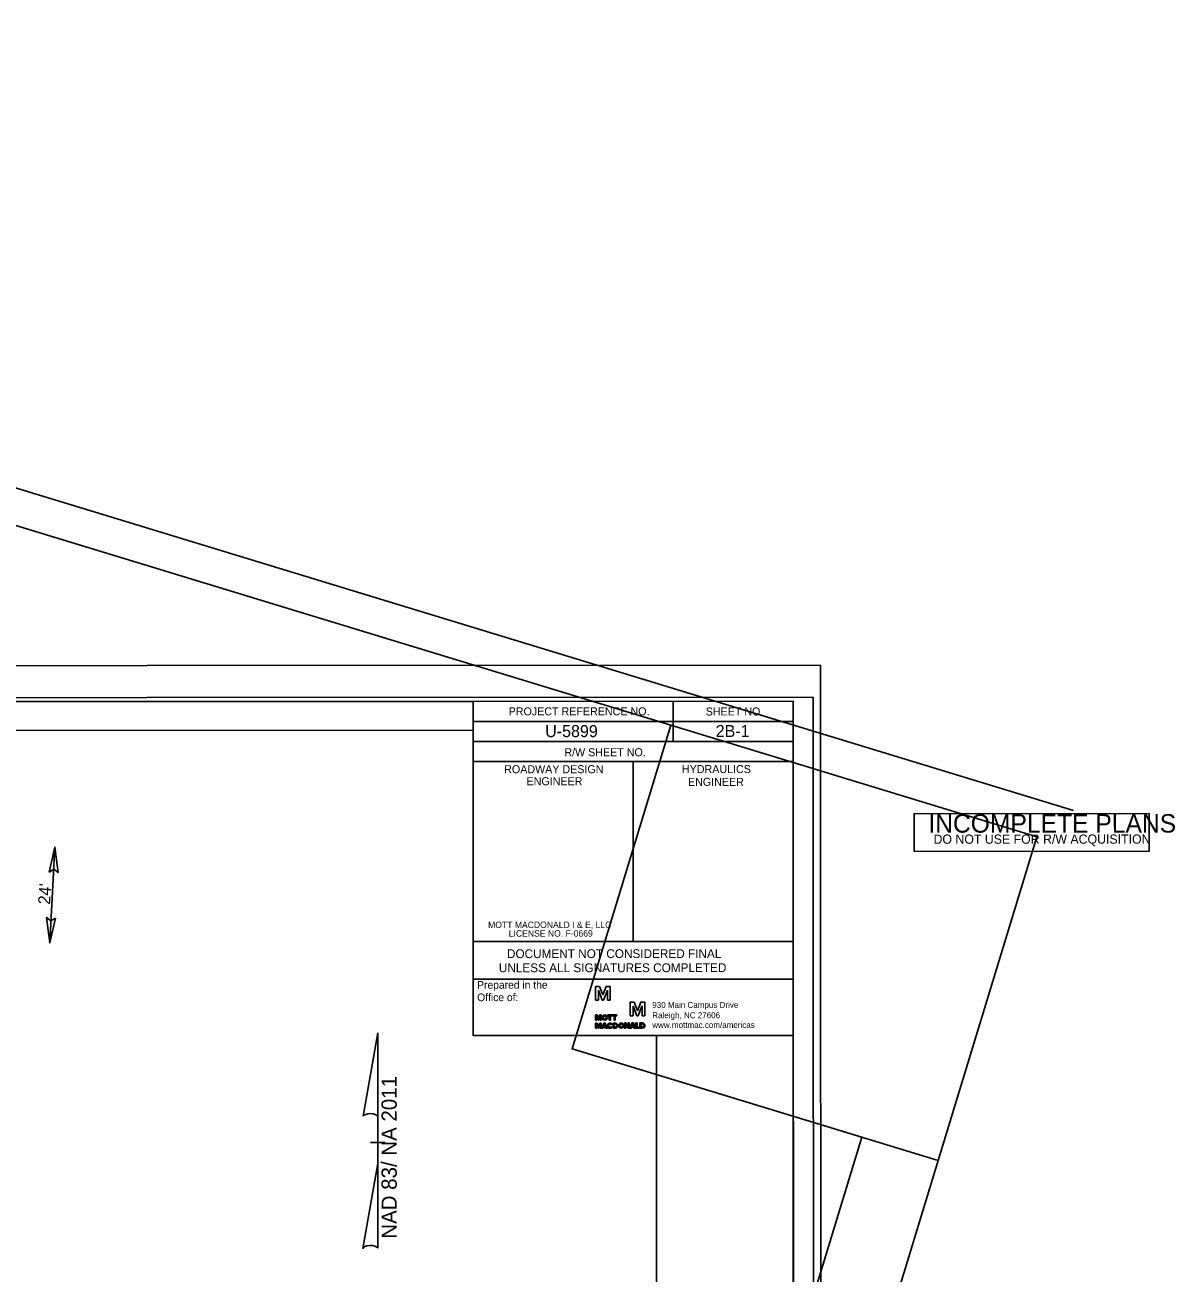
# Model space of a CAD drawing. Extents: x 1443477 to 1619989, y 756574 to 899826.
# Drawn here: x 1619701.9 to 1619989.5, y 898108 to 898420 of the extents above; entities that cross this region are included whole.
import ezdxf

# ---------------------------------------------------------------- set-up
doc = ezdxf.new("R2010")
doc.units = 0
for name, color, linetype in [('Default', 7, 'Continuous'), ('Old_Level_2', 7, 'Continuous'), ('Old_Level_42', 7, 'Continuous'), ('Old_Level_45', 7, 'Continuous'), ('Prop Dimension', 7, 'Continuous'), ('Prop North Arrow NAD83 for Plan Sheets CELL', 7, 'Continuous'), ('Prop Terminator CELL', 7, 'Continuous'), ('Sheet Clip Boundary CELL', 7, 'Continuous'), ('Sheet Cutting Line CELL', 7, 'Continuous'), ('Sheet Data Field CELL', 7, 'Continuous'), ('Sheet Layout Plan Border', 7, 'Continuous'), ('Sheet Plan CELL', 7, 'Continuous'), ('Sheet Plan Layout CELL', 7, 'Continuous'), ('Sheet Plot Border Inside CELL', 7, 'Continuous'), ('Sheet Plot Border Outside CELL', 7, 'Continuous'), ('Sheet Sticker Exception Certification CELL', 7, 'Continuous'), ('Sheet Sticker Incomplete CELL', 7, 'Continuous')]:
    doc.layers.add(name, color=color, linetype=linetype)

msp = doc.modelspace()

# ---------------------------------------------------------------- linework, layer by layer
at = {"layer": 'Default'}
msp.add_lwpolyline([(1619324.8, 898243.59), (1619813.94, 898243.79), (1619813.98, 898167.39), (1619859.81, 898167.41), (1619859.94, 897863.4), (1619324.96, 897863.18)], close=True, dxfattribs=at)
at = {"layer": 'Old_Level_2'}
for p, q in [((1619845.57, 898179.68), (1619844.56, 898179.68)), ((1619844.56, 898179.68), (1619844.56, 898176.28)), ((1619846.39, 898177.58), (1619845.57, 898179.68)), ((1619847.23, 898179.68), (1619846.41, 898177.58)), ((1619848.24, 898179.68), (1619847.23, 898179.68)), ((1619848.24, 898176.28), (1619848.24, 898179.68)), ((1619844.56, 898176.28), (1619845.28, 898176.28)), ((1619845.28, 898176.28), (1619845.28, 898178.73)), ((1619845.28, 898178.73), (1619845.29, 898178.73)), ((1619845.29, 898178.73), (1619846.24, 898176.28)), ((1619846.24, 898176.28), (1619846.56, 898176.28)), ((1619846.39, 898177.55), (1619846.39, 898177.58)), ((1619846.41, 898177.55), (1619846.39, 898177.55)), ((1619846.41, 898177.58), (1619846.41, 898177.55)), ((1619846.56, 898176.28), (1619847.51, 898178.74)), ((1619847.51, 898178.74), (1619847.52, 898178.74)), ((1619847.52, 898178.74), (1619847.52, 898176.28)), ((1619847.52, 898176.28), (1619848.24, 898176.28)), ((1619854.21, 898175.72), (1619853.21, 898175.72)), ((1619853.21, 898175.72), (1619853.21, 898172.32)), ((1619853.92, 898172.32), (1619853.92, 898174.77)), ((1619853.92, 898174.77), (1619853.93, 898174.77)), ((1619853.93, 898174.77), (1619854.89, 898172.32)), ((1619855.04, 898173.62), (1619854.21, 898175.72)), ((1619855.04, 898173.59), (1619855.04, 898173.62)), ((1619855.06, 898173.59), (1619855.04, 898173.59)), ((1619855.88, 898175.73), (1619855.06, 898173.62)), ((1619855.06, 898173.62), (1619855.06, 898173.59)), ((1619855.2, 898172.32), (1619856.16, 898174.78)), ((1619856.89, 898175.73), (1619855.88, 898175.73)), ((1619856.16, 898174.78), (1619856.17, 898174.78)), ((1619856.17, 898174.78), (1619856.17, 898172.33)), ((1619856.89, 898172.33), (1619856.89, 898175.73)), ((1619844.95, 898172.56), (1619844.56, 898172.56)), ((1619844.56, 898172.56), (1619844.56, 898171.26)), ((1619844.56, 898171.26), (1619844.83, 898171.26)), ((1619844.95, 898170.54), (1619844.56, 898170.54)), ((1619844.56, 898170.54), (1619844.56, 898169.24)), ((1619844.83, 898171.26), (1619844.83, 898172.2)), ((1619844.83, 898172.2), (1619844.84, 898172.2)), ((1619844.83, 898172.2), (1619844.84, 898172.2)), ((1619844.83, 898169.24), (1619844.83, 898170.18)), ((1619844.83, 898170.18), (1619844.84, 898170.18)), ((1619844.84, 898172.2), (1619845.21, 898171.26)), ((1619844.84, 898170.18), (1619845.21, 898169.24)), ((1619845.27, 898171.75), (1619844.95, 898172.56)), ((1619845.27, 898169.73), (1619844.95, 898170.54)), ((1619845.21, 898171.26), (1619845.33, 898171.26)), ((1619845.59, 898172.56), (1619845.27, 898171.75)), ((1619845.59, 898170.54), (1619845.27, 898169.73)), ((1619845.33, 898171.26), (1619845.69, 898172.2)), ((1619845.33, 898169.24), (1619845.7, 898170.18)), ((1619845.98, 898172.56), (1619845.59, 898172.56)), ((1619845.98, 898170.54), (1619845.59, 898170.54)), ((1619845.69, 898172.2), (1619845.7, 898172.2)), ((1619845.69, 898172.2), (1619845.7, 898172.2)), ((1619845.69, 898172.2), (1619845.7, 898172.2)), ((1619845.7, 898172.2), (1619845.71, 898171.26)), ((1619845.7, 898170.18), (1619845.71, 898170.18)), ((1619845.71, 898171.26), (1619845.98, 898171.26)), ((1619845.71, 898170.18), (1619845.71, 898169.24)), ((1619845.98, 898171.26), (1619845.98, 898172.56)), ((1619845.98, 898169.24), (1619845.98, 898170.54)), ((1619848.51, 898170.12), (1619848.74, 898170.23)), ((1619849.51, 898170.54), (1619848.92, 898170.54)), ((1619848.92, 898170.54), (1619848.92, 898169.87)), ((1619848.92, 898169.87), (1619848.92, 898169.24)), ((1619849.19, 898169.49), (1619849.19, 898170.3)), ((1619849.19, 898170.3), (1619849.51, 898170.3)), ((1619853.21, 898172.32), (1619853.92, 898172.32)), ((1619854.89, 898172.32), (1619855.2, 898172.32)), ((1619855.65, 898170.55), (1619855.65, 898170.55)), ((1619856.24, 898170.55), (1619855.65, 898170.55)), ((1619855.65, 898170.55), (1619855.65, 898169.87)), ((1619855.65, 898169.87), (1619855.65, 898169.25)), ((1619855.92, 898169.5), (1619855.92, 898170.31)), ((1619855.92, 898170.31), (1619856.24, 898170.31)), ((1619856.17, 898172.33), (1619856.89, 898172.33)), ((1619856.24, 898170.3), (1619856.24, 898170.3)), ((1619844.56, 898169.24), (1619844.83, 898169.24)), ((1619845.21, 898169.24), (1619845.33, 898169.24)), ((1619845.71, 898169.24), (1619845.98, 898169.24)), ((1619848.71, 898169.51), (1619848.48, 898169.62)), ((1619848.92, 898169.24), (1619849.51, 898169.24)), ((1619849.51, 898169.49), (1619849.19, 898169.49)), ((1619855.65, 898169.25), (1619856.24, 898169.25)), ((1619856.24, 898169.5), (1619855.92, 898169.5))]:
    msp.add_line(p, q, dxfattribs=at)
for points in [[(1619846.13, 898169.24), (1619846.44, 898169.24), (1619846.53, 898169.46), (1619847.09, 898169.46), (1619847.17, 898169.24), (1619847.47, 898169.24), (1619846.97, 898170.54), (1619846.63, 898170.54), (1619846.13, 898169.24)], [(1619846.6, 898169.7), (1619846.81, 898170.26), (1619847.02, 898169.7), (1619846.6, 898169.7)], [(1619847.61, 898172.32), (1619847.98, 898172.32), (1619847.98, 898171.26), (1619848.26, 898171.26), (1619848.26, 898172.32), (1619848.64, 898172.32), (1619848.64, 898172.56), (1619847.61, 898172.56), (1619847.61, 898172.32)], [(1619848.8, 898172.32), (1619849.18, 898172.32), (1619849.18, 898171.26), (1619849.46, 898171.26), (1619849.46, 898172.32), (1619849.83, 898172.32), (1619849.83, 898172.56), (1619848.8, 898172.56), (1619848.8, 898172.32)], [(1619852.1, 898170.09), (1619852.11, 898170.09), (1619852.74, 898169.25), (1619853, 898169.25), (1619852.99, 898170.55), (1619852.72, 898170.55), (1619852.72, 898169.72), (1619852.11, 898170.55), (1619851.84, 898170.55), (1619851.84, 898169.25), (1619852.1, 898169.25), (1619852.1, 898170.09)], [(1619853.16, 898169.25), (1619853.47, 898169.25), (1619853.56, 898169.46), (1619854.12, 898169.47), (1619854.2, 898169.25), (1619854.5, 898169.25), (1619854, 898170.55), (1619853.66, 898170.55), (1619853.16, 898169.25)], [(1619853.63, 898169.7), (1619853.84, 898170.27), (1619854.04, 898169.7), (1619853.63, 898169.7)], [(1619855.49, 898169.25), (1619855.49, 898169.48), (1619854.93, 898169.48), (1619854.93, 898170.55), (1619854.66, 898170.55), (1619854.66, 898169.25), (1619855.49, 898169.25)]]:
    msp.add_lwpolyline(points, dxfattribs=at)
msp.add_arc((1619856.24, 898169.9), 0.65, 270.0239, 90.0239, dxfattribs=at)
for centre, major_axis, ratio in [((1619846.86, 898171.91), (0, 0.65), 0.993118), ((1619846.86, 898171.91), (0, 0.423), 0.916103), ((1619850.97, 898169.9), (0, 0.65), 0.993118), ((1619850.97, 898169.9), (0, 0.423), 0.916103)]:
    msp.add_ellipse(centre, major_axis=major_axis, ratio=ratio, dxfattribs=at)
for centre, major_axis, ratio, start_param, end_param in [((1619848.18, 898169.89), (0, 0.65), 0.993118, 5.246647, 10.366427), ((1619848.18, 898169.89), (0, 0.423), 0.916103, 5.276876, 10.296021), ((1619849.51, 898169.89), (0, -0.649), 0.930276, 0, 3.141593), ((1619849.51, 898169.9), (0, -0.405), 0.900832, 0, 3.141593), ((1619856.24, 898169.9), (0, -0.405), 0.900832, 0, 3.141593)]:
    msp.add_ellipse(centre, major_axis=major_axis, ratio=ratio, start_param=start_param, end_param=end_param, dxfattribs=at)
at = {"layer": 'Old_Level_42'}
msp.add_lwpolyline([(1619894, 898167.42), (1619813.98, 898167.39), (1619813.97, 898181.51)], dxfattribs=at)
at = {"layer": 'Prop Dimension'}
msp.add_line((1619709.38, 898214.52), (1619708.05, 898190.55), dxfattribs=at)
at = {"layer": 'Prop North Arrow NAD83 for Plan Sheets CELL'}
for p, q in [((1619786.4, 898147.23), (1619790.09, 898168.09)), ((1619790.12, 898168.09), (1619790.09, 898168.09)), ((1619790.12, 898168.09), (1619790.09, 898168.09)), ((1619790.12, 898168.09), (1619790.12, 898146.58)), ((1619790.12, 898135.42), (1619790.12, 898147.21)), ((1619790.12, 898146.58), (1619790.12, 898147.18)), ((1619788.32, 898140.64), (1619788.29, 898140.64)), ((1619789.91, 898140.64), (1619788.32, 898140.64)), ((1619788.34, 898140.64), (1619791.94, 898140.64)), ((1619790.12, 898135.42), (1619786.36, 898114.15)), ((1619790.14, 898114.24), (1619790.12, 898135.42))]:
    msp.add_line(p, q, dxfattribs=at)
for centre, start_param, end_param in [((1619788.26, 898147.01), 0.216388, 2.908219), ((1619788.26, 898114.08), 0.201328, 3.141593)]:
    msp.add_ellipse(centre, major_axis=(1.9, -0.01), ratio=0.461098, start_param=start_param, end_param=end_param, dxfattribs=at)
at = {"layer": 'Prop Terminator CELL'}
for points in [[(1619707.95, 898208.29), (1619709.38, 898214.52), (1619710.15, 898208.13), (1619709.08, 898209)], [(1619709.48, 898196.78), (1619708.05, 898190.55), (1619707.28, 898196.94), (1619708.36, 898196.08)]]:
    msp.add_lwpolyline(points, close=True, dxfattribs=at)
at = {"layer": 'Sheet Clip Boundary CELL'}
msp.add_lwpolyline([(1619277.64, 897984.43), (1619813.32, 897821.17), (1619911.11, 898142), (1619838.69, 898164.07), (1619863.35, 898244.99), (1619400.09, 898386.19)], close=True, dxfattribs=at)
at = {"layer": 'Sheet Cutting Line CELL'}
msp.add_line((1619964.03, 898223.71), (1619319.88, 898420.04), dxfattribs=at)
at = {"layer": 'Sheet Layout Plan Border'}
msp.add_lwpolyline([(1619277.64, 897984.43), (1619813.32, 897821.17), (1619911.11, 898142), (1619838.69, 898164.07), (1619863.35, 898244.99), (1619400.09, 898386.19)], close=True, dxfattribs=at)
at = {"layer": 'Sheet Plan CELL'}
for p, q in [((1619863.94, 898250.93), (1619863.97, 898240.93)), ((1619813.94, 898245.91), (1619893.96, 898245.94)), ((1619813.94, 898240.9), (1619893.96, 898240.94)), ((1619813.94, 898240.9), (1619893.96, 898240.94)), ((1619853.97, 898235.92), (1619853.99, 898190.94))]:
    msp.add_line(p, q, dxfattribs=at)
for points in [[(1619294.13, 897830.71), (1619293.94, 898250.7), (1619813.94, 898250.93), (1619813.97, 898190.91), (1619893.98, 898190.94), (1619894.13, 897830.96)], [(1619893.97, 898250.96), (1619293.95, 898250.71), (1619294.13, 897830.71), (1619894.13, 897830.96)], [(1619813.94, 898250.93), (1619893.97, 898250.96), (1619893.96, 898240.94), (1619813.94, 898240.9)], [(1619813.95, 898235.9), (1619853.97, 898235.92), (1619853.98, 898190.92), (1619813.97, 898190.91)], [(1619853.97, 898235.92), (1619893.96, 898235.94), (1619893.98, 898190.94), (1619853.98, 898190.92)]]:
    msp.add_lwpolyline(points, close=True, dxfattribs=at)
at = {"layer": 'Sheet Plan Layout CELL'}
for points in [[(1619380.95, 898392.01), (1619258.51, 897990.27), (1619832.45, 897815.34), (1619930.23, 898136.17), (1619838.69, 898164.07), (1619863.35, 898244.99)], [(1619838.69, 898164.07), (1619930.24, 898136.17), (1619954.92, 898217.09), (1619863.35, 898244.99)]]:
    msp.add_lwpolyline(points, close=True, dxfattribs=at)
at = {"layer": 'Sheet Plot Border Inside CELL'}
msp.add_lwpolyline([(1619232.74, 897829.68), (1619899.13, 897829.97), (1619898.96, 898251.96), (1619232.56, 898251.68)], close=True, dxfattribs=at)
at = {"layer": 'Sheet Plot Border Outside CELL'}
msp.add_lwpolyline([(1619227.54, 897821.68), (1619900.94, 897821.96), (1619900.76, 898259.96), (1619227.36, 898259.68)], close=True, dxfattribs=at)
at = {"layer": 'Sheet Sticker Exception Certification CELL'}
for p, q in [((1619813.97, 898190.91), (1619893.98, 898190.94)), ((1619813.97, 898190.91), (1619893.98, 898190.94)), ((1619813.97, 898181.51), (1619813.97, 898190.91)), ((1619813.97, 898181.51), (1619813.97, 898190.91)), ((1619893.98, 898190.94), (1619893.99, 898181.54)), ((1619893.98, 898190.94), (1619893.99, 898181.54)), ((1619893.99, 898181.54), (1619813.97, 898181.51)), ((1619893.99, 898181.54), (1619813.97, 898181.51))]:
    msp.add_line(p, q, dxfattribs=at)
at = {"layer": 'Sheet Sticker Incomplete CELL'}
msp.add_lwpolyline([(1619924.18, 898213.45), (1619924.18, 898222.85), (1619982.98, 898222.88), (1619982.98, 898213.48)], close=True, dxfattribs=at)

# ---------------------------------------------------------------- texts
at = {"layer": 'Old_Level_2'}
for s, height, p in [('Prepared in the ', 1.9274, (1619814.94, 898179.11)), ('Office of:', 1.927, (1619814.94, 898176.01)), ('930 Main Campus Drive', 1.5, (1619858.73, 898174.32)), ('Raleigh, NC 27606', 1.5, (1619858.73, 898171.74)), ('www.mottmac.com/americas', 1.5, (1619858.73, 898169.3))]:
    msp.add_text(s, height=height, rotation=0.0239, dxfattribs=at).set_placement(p)
at = {"layer": 'Old_Level_45'}
for s, p in [('MOTT MACDONALD I & E, LLC', (1619817.68, 898194.28)), (' LICENSE NO. F-0669', (1619822.24, 898192.14))]:
    msp.add_text(s, height=1.6071, rotation=0.0239, dxfattribs=at).set_placement(p)
at = {"layer": 'Prop Dimension'}
msp.add_text("24'", height=3, rotation=86.3635, dxfattribs=at).set_placement((1619708.13, 898200.1))
at = {"layer": 'Prop North Arrow NAD83 for Plan Sheets CELL'}
msp.add_text('NAD 83/ NA 2011', height=3.825, rotation=90, dxfattribs=at).set_placement((1619794.85, 898116.63))
at = {"layer": 'Sheet Data Field CELL'}
for s, p in [('U-5899', (1619831.95, 898242.01)), ('2B-1', (1619874.59, 898242.05))]:
    msp.add_text(s, height=3, rotation=0.0239, dxfattribs=at).set_placement(p)
at = {"layer": 'Sheet Plan CELL'}
for s, p in [('PROJECT REFERENCE NO.', (1619822.82, 898247.45)), ('SHEET NO.', (1619872.09, 898247.42)), ('R/W SHEET NO.', (1619836.75, 898237.23)), ('ROADWAY DESIGN', (1619821.7, 898232.99)), ('HYDRAULICS', (1619866.15, 898233.02)), ('ENGINEER', (1619827.29, 898229.98)), ('ENGINEER', (1619867.66, 898229.83))]:
    msp.add_text(s, height=2, rotation=0.0239, dxfattribs=at).set_placement(p)
at = {"layer": 'Sheet Sticker Exception Certification CELL'}
for s, p in [('DOCUMENT NOT CONSIDERED FINAL', (1619822.4, 898186.77)), ('DOCUMENT NOT CONSIDERED FINAL', (1619822.4, 898186.77)), ('UNLESS ALL SIGNATURES COMPLETED', (1619820.37, 898183.25)), ('UNLESS ALL SIGNATURES COMPLETED', (1619820.37, 898183.25))]:
    msp.add_text(s, height=2.2, rotation=0.0239, dxfattribs=at).set_placement(p)
at = {"layer": 'Sheet Sticker Incomplete CELL'}
for s, height, p in [('INCOMPLETE PLANS', 4.608, (1619927.76, 898218.13)), ('DO NOT USE FOR R/W ACQUISITION', 2.304, (1619929.06, 898215.35))]:
    msp.add_text(s, height=height, rotation=0.0239, dxfattribs=at).set_placement(p)

doc.saveas('drawing.dxf')
